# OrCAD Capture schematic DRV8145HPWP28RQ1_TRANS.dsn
size Custom; title: DRV8145-Q1 Automotive Half Bridge Driver with; rev: 1.0; note: Datasheet: SLVSG22      EVM: NA; note: Synchronous Step Down Converter
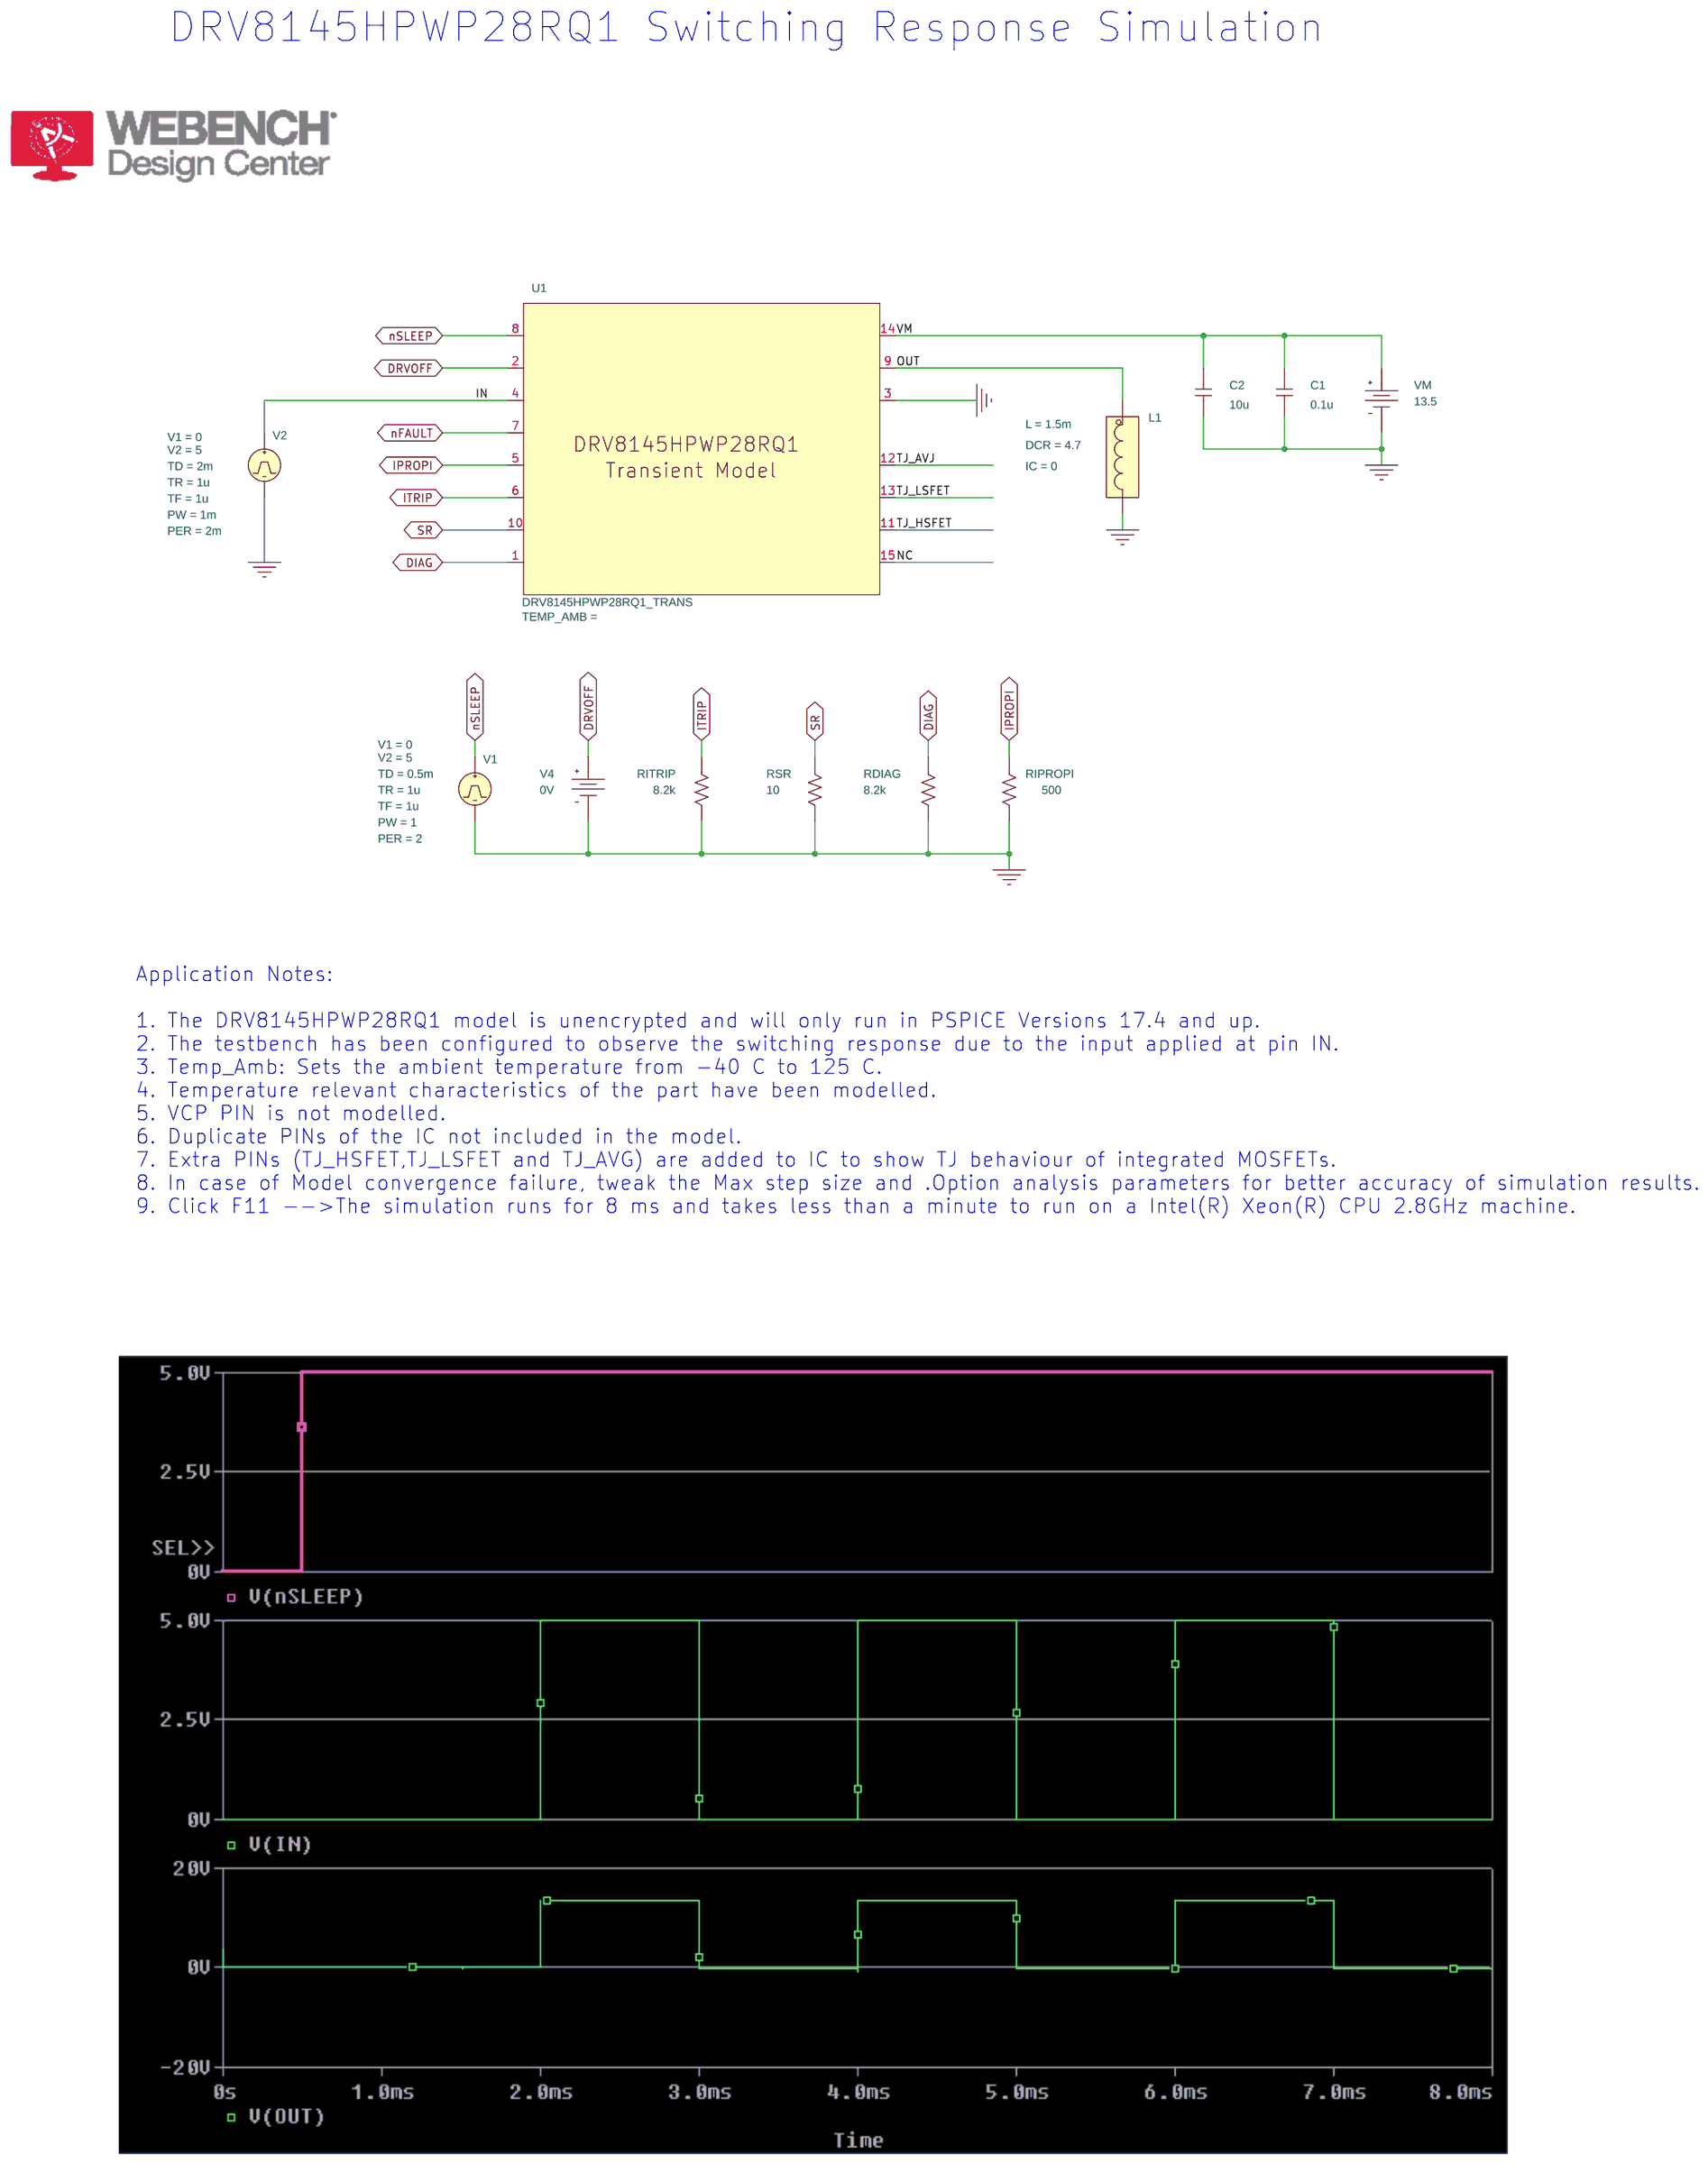
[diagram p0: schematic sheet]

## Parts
C1  0.1u  [RAD/CK05]
C2  10u  [RAD/CK05]
L1  LDCR
RDIAG  8.2k  [AXRC05]
RIPROPI  500  [AXRC05]
RITRIP  8.2k  [AXRC05]
RSR  10  [AXRC05]
U1  DRV8145HPWP28RQ1_TRANS
V1  VPULSE
V2  VPULSE
V4  VDC
VM  VDC

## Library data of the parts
C1 C2 = C
L1 = LDCR: DCR: 4.7; IC: 0; L: 1.5m; PSpiceTemplate: X^@REFDES %IN %OUT @MODEL PARAMS:  ?L|L=@L||L=1u|  ?DCR|DCR=@DCR||DCR=0.01| ?IC|IC=@IC||IC=0|
RDIAG RIPROPI RITRIP RSR = R
U1 = DRV8145HPWP28RQ1_TRANS
V1 = VPULSE: PER: 2; PW: 1; TD: 0.5m; TF: 1u; TR: 1u; V1: 0; V2: 5
V2 = VPULSE: PER: 2m; PW: 1m; TD: 2m; TF: 1u; TR: 1u; V1: 0; V2: 5
V4 = VDC: DC: 0V
VM = VDC: DC: 13.5

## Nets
0: C1.2 C2.2 L1.3(OUT) RDIAG.2 RIPROPI.2 RITRIP.2 RSR.2 U1.3(GND) V1.2(-) V2.2(-) V4.1(-) VM.1(-)
DIAG: RDIAG.1 U1.1(DIAG)
DRVOFF: U1.2(DRVOFF) V4.0(+)
IN: U1.4(IN) V2.1(+)
IPROPI: RIPROPI.1 U1.5(IPROPI)
ITRIP: RITRIP.1 U1.6(ITRIP)
NC: U1.15(NC)
nFAULT: U1.7(nFAULT)
nSLEEP: U1.8(nSLEEP) V1.1(+)
OUT: L1.1(IN) U1.9(OUT)
SR: RSR.1 U1.10(SR)
TJ_AVJ: U1.12(TJ_HSFET)
TJ_HSFET: U1.11(TJ_AVG)
TJ_LSFET: U1.13(TJ_LSFET)
VM: C1.1 C2.1 U1.14(VM) VM.0(+)

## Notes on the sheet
- DRV8145HPWP28RQ1 Switching Response Simulation
- Application Notes:
  1. The DRV8145HPWP28RQ1 model is unencrypted and will only run in PSPICE Versions 17.4 and up.
  2. The testbench has been configured to observe the switching response due to the input applied at pin IN.
  3. Temp_Amb: Sets the ambient temperature from -40 C to 125 C.
  4. Temperature relevant characteristics of the part have been modelled.
  5. VCP PIN is not modelled.
  6. Duplicate PINs of the IC not included in the model.
  7. Extra PINs (TJ_HSFET,TJ_LSFET and TJ_AVG) are added to IC to show TJ behaviour of integrated MOSFETs.
  8. In case of Model convergence failure, tweak the Max step size and .Option analysis parameters for better accuracy of simulation results.
  9. Click F11 -->The simulation runs for 8 ms and takes less than a minute to run on a Intel(R) Xeon(R) CPU 2.8GHz machine.
